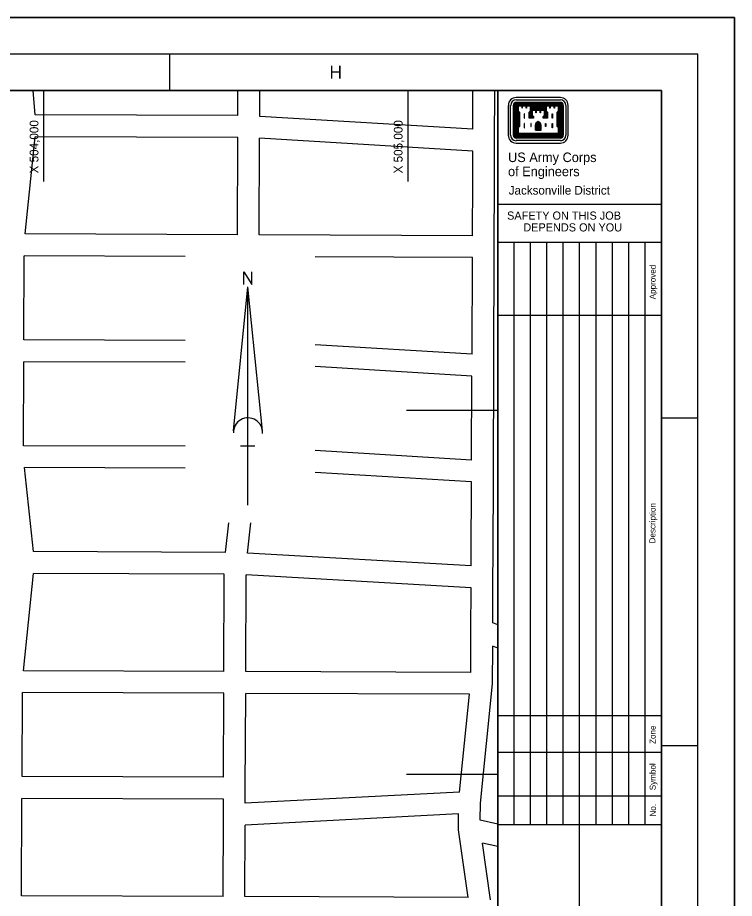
# Model space of a CAD drawing. Extents: x 497696 to 505896, y 1319278 to 1325078.
# Drawn here: x 503928 to 505896, y 1322658 to 1325078 of the extents above; entities that cross this region are included whole.
import ezdxf

# ---------------------------------------------------------------- set-up
doc = ezdxf.new("R2010")
doc.units = 0
for name, color, linetype in [('G-ANNO-SYMB', 7, 'Continuous'), ('G-ANNO-TEXT', 7, 'Continuous'), ('G-ANNO-TTLB', 7, 'Continuous'), ('Level 1', 7, 'Continuous'), ('Level 2', 7, 'Continuous'), ('Level 3', 7, 'Continuous'), ('Level 32', 7, 'Continuous')]:
    doc.layers.add(name, color=color, linetype=linetype)

msp = doc.modelspace()

# ---------------------------------------------------------------- linework, layer by layer
at = {"layer": 'G-ANNO-SYMB'}
for p, q in [((505418.4, 1324858.3), (505296.8, 1324858.3)), ((505275.4, 1324836.9), (505275.4, 1324754.9)), ((505281.8, 1324754.9), (505281.8, 1324836.9)), ((505288.8, 1324836.9), (505288.8, 1324754.9)), ((505290.6, 1324836.9), (505290.6, 1324754.9)), ((505292.2, 1324836.9), (505292.2, 1324754.9)), ((505294, 1324836.9), (505294, 1324754.9)), ((505295.8, 1324836.9), (505295.8, 1324754.9)), ((505296.8, 1324851.9), (505418.4, 1324851.9)), ((505418.4, 1324845.1), (505296.8, 1324845.1)), ((505418.4, 1324843.3), (505296.8, 1324843.3)), ((505418.4, 1324841.5), (505296.8, 1324841.5)), ((505418.4, 1324839.9), (505296.8, 1324839.9)), ((505418.4, 1324838.1), (505296.8, 1324838.1)), ((505297.6, 1324836.9), (505297.6, 1324755.5)), ((505299.2, 1324836.9), (505299.2, 1324757.3)), ((505339, 1324836.5), (505376.2, 1324836.5)), ((505339, 1324834.7), (505376.2, 1324834.7)), ((505339, 1324833.1), (505376.2, 1324833.1)), ((505339, 1324831.3), (505376.2, 1324831.3)), ((505339, 1324829.5), (505376.2, 1324829.5)), ((505416, 1324836.9), (505416, 1324757.3)), ((505417.6, 1324836.9), (505417.6, 1324755.5)), ((505419.4, 1324836.9), (505419.4, 1324754.9)), ((505421.2, 1324836.9), (505421.2, 1324754.9)), ((505422.8, 1324836.9), (505422.8, 1324754.9)), ((505424.6, 1324836.9), (505424.6, 1324754.9)), ((505426.4, 1324836.9), (505426.4, 1324754.9)), ((505433.2, 1324836.9), (505433.2, 1324754.9)), ((505439.8, 1324754.9), (505439.8, 1324836.9)), ((505300.6, 1324819.5), (505300.6, 1324777.5)), ((505302.4, 1324817.7), (505302.4, 1324779.5)), ((505339, 1324827.9), (505376.2, 1324827.9)), ((505339, 1324826.1), (505376.2, 1324826.1)), ((505412.8, 1324817.7), (505412.8, 1324779.5)), ((505414.6, 1324819.3), (505414.6, 1324777.7)), ((505349.6, 1324769.1), (505349.6, 1324782.5)), ((505351.2, 1324769.1), (505351.2, 1324782.5)), ((505353, 1324769.1), (505353, 1324782.5)), ((505354.8, 1324769.1), (505354.8, 1324782.5)), ((505356.4, 1324769.1), (505356.4, 1324782.5)), ((505358.8, 1324769.1), (505358.8, 1324782.5)), ((505360.4, 1324769.1), (505360.4, 1324782.5)), ((505362.2, 1324769.1), (505362.2, 1324782.5)), ((505364, 1324769.1), (505364, 1324782.5)), ((505365.6, 1324769.1), (505365.6, 1324782.5)), ((505416, 1324757.3), (505299.2, 1324757.3)), ((505349.6, 1324769.1), (505365.6, 1324769.1)), ((505418.4, 1324753.7), (505296.8, 1324753.7)), ((505418.4, 1324752.1), (505296.8, 1324752.1)), ((505418.4, 1324750.3), (505296.8, 1324750.3)), ((505418.4, 1324748.5), (505296.8, 1324748.5)), ((505418.4, 1324746.9), (505296.8, 1324746.9)), ((505418.4, 1324739.9), (505296.8, 1324739.9)), ((505296.8, 1324733.3), (505418.4, 1324733.3)), ((505417.6, 1324755.5), (505297.6, 1324755.5))]:
    msp.add_line(p, q, dxfattribs=at)
for points in [[(505300.6, 1324836.9), (505300.6, 1324821.1), (505304, 1324817.7), (505304, 1324779.5), (505300.6, 1324775.9), (505300.6, 1324758.5), (505414.6, 1324758.5), (505414.6, 1324775.9), (505411, 1324779.5), (505411, 1324817.7), (505414.6, 1324821.1), (505414.6, 1324836.9), (505399.6, 1324836.9), (505388, 1324836.9), (505377.2, 1324836.9), (505377.2, 1324821.1), (505381, 1324817.7), (505381, 1324803.7), (505372.6, 1324803.7), (505372.6, 1324805.1), (505376.2, 1324808.7), (505376.2, 1324824.3), (505361.2, 1324824.3), (505349.6, 1324824.3), (505339, 1324824.3), (505339, 1324808.7), (505342.6, 1324805.1), (505342.6, 1324803.7), (505334.2, 1324803.7), (505334.2, 1324817.7), (505337.8, 1324821.1), (505337.8, 1324836.9), (505322.8, 1324836.9), (505311.2, 1324836.9), (505300.6, 1324836.9)], [(505302.2, 1324835.1), (505302.2, 1324821.9), (505305.8, 1324818.3), (505305.8, 1324778.7), (505302.2, 1324775.1), (505302.2, 1324760.3), (505413, 1324760.3), (505413, 1324775.1), (505409.2, 1324778.7), (505409.2, 1324818.3), (505413, 1324821.9), (505413, 1324835.1), (505402.2, 1324835.1), (505402.2, 1324828.9), (505401.2, 1324828.9), (505401.2, 1324835.1), (505390.6, 1324835.1), (505390.6, 1324828.9), (505389.8, 1324828.9), (505389.8, 1324835.1), (505379, 1324835.1), (505379, 1324821.9), (505382.6, 1324818.3), (505382.6, 1324802.1), (505371, 1324802.1), (505371, 1324805.9), (505374.6, 1324809.5), (505374.6, 1324822.7), (505363.8, 1324822.7), (505363.8, 1324816.5), (505363, 1324816.5), (505363, 1324822.7), (505352.2, 1324822.7), (505352.2, 1324816.5), (505351.2, 1324816.5), (505351.2, 1324822.7), (505340.6, 1324822.7), (505340.6, 1324809.5), (505344.2, 1324805.9), (505344.2, 1324802.1), (505332.6, 1324802.1), (505332.6, 1324818.3), (505336.2, 1324821.9), (505336.2, 1324835.1), (505325.6, 1324835.1), (505325.6, 1324828.9), (505324.6, 1324828.9), (505324.6, 1324835.1), (505313.8, 1324835.1), (505313.8, 1324828.9), (505313, 1324828.9), (505313, 1324835.1), (505302.2, 1324835.1)], [(505318.6, 1324813.7), (505318.6, 1324802.1), (505319.8, 1324802.1), (505319.8, 1324813.7), (505318.6, 1324813.7)], [(505337, 1324817.9), (505336, 1324816.9), (505336, 1324805.5), (505339.8, 1324805.5), (505337.2, 1324808.1), (505337.2, 1324818.1)], [(505378.2, 1324817.9), (505379.2, 1324816.9), (505379.2, 1324805.5), (505375.6, 1324805.5), (505378, 1324808.1), (505378, 1324818.1)], [(505396.4, 1324813.7), (505396.4, 1324802.1), (505395.4, 1324802.1), (505395.4, 1324813.7), (505396.4, 1324813.7)], [(505318.6, 1324787.1), (505318.6, 1324775.3), (505319.8, 1324775.3), (505319.8, 1324787.1), (505318.6, 1324787.1)], [(505337, 1324787.1), (505337, 1324778.9), (505338, 1324778.9), (505338, 1324787.1), (505337, 1324787.1)], [(505378.2, 1324787.1), (505378.2, 1324778.9), (505377.2, 1324778.9), (505377.2, 1324787.1), (505378.2, 1324787.1)], [(505396.4, 1324787.1), (505396.4, 1324775.3), (505395.4, 1324775.3), (505395.4, 1324787.1), (505396.4, 1324787.1)]]:
    msp.add_lwpolyline(points, dxfattribs=at)
for centre, major_axis, start_param, end_param in [((505296.9, 1324836.9), (21.4, 0), 1.57078, 3.141576), ((505418.3, 1324836.9), (21.4, 0), 6.283169, 7.853965), ((505296.9, 1324836.9), (15, 0), 1.57078, 3.141576), ((505296.9, 1324836.9), (8.04, 0), 1.57078, 3.141576), ((505296.9, 1324836.9), (6.3, 0), 1.57078, 3.141576), ((505296.9, 1324836.9), (4.56, 0), 1.57078, 3.141576), ((505296.9, 1324836.9), (2.83, 0), 1.57078, 3.141576), ((505296.9, 1324836.9), (1.09, 0), 1.57078, 3.141576), ((505418.3, 1324836.9), (15, 0), 6.28317, 7.853966), ((505418.3, 1324836.9), (8.04, 0), 6.283169, 7.853965), ((505418.3, 1324836.9), (6.3, 0), 6.283169, 7.853965), ((505418.3, 1324836.9), (4.56, 0), 6.283169, 7.853965), ((505418.3, 1324836.9), (2.83, 0), 6.283169, 7.853965), ((505418.3, 1324836.9), (1.09, 0), 6.283169, 7.853965), ((505360.6, 1324781.6), (-11.1, 0), 4.985832, 6.214359), ((505360.6, 1324781.6), (-9.37, 0), 4.947465, 6.21436), ((505360.6, 1324781.6), (-7.63, 0), 4.947465, 6.21436), ((505360.6, 1324781.6), (-5.9, 0), 4.947465, 6.21436), ((505354.6, 1324781.6), (4.16, 0), 0.068794, 1.335689), ((505354.6, 1324781.6), (5.9, 0), 0.068794, 1.335689), ((505354.6, 1324781.6), (7.63, 0), 0.068795, 1.335689), ((505360.6, 1324781.6), (-4.16, 0), 4.947465, 6.214359), ((505354.6, 1324781.6), (9.37, 0), 0.068795, 1.335689), ((505354.6, 1324781.6), (11.1, 0), 0.068795, 1.29842), ((505296.8, 1324754.8), (-21.4, 0), 6.28317, 7.853966), ((505296.8, 1324754.8), (-15, 0), 6.28317, 7.853966), ((505296.8, 1324754.8), (-8.04, 0), 6.28317, 7.853966), ((505296.8, 1324754.8), (-6.3, 0), 6.28317, 7.853966), ((505296.8, 1324754.8), (-4.56, 0), 6.28317, 7.853966), ((505296.8, 1324754.8), (-2.83, 0), 6.28317, 7.853966), ((505296.8, 1324754.8), (-1.09, 0), 6.28317, 7.853966), ((505418.3, 1324754.8), (8.04, 0), 4.712373, 6.28317), ((505418.3, 1324754.8), (6.3, 0), 4.712373, 6.28317), ((505418.3, 1324754.8), (4.56, 0), 4.712373, 6.28317), ((505418.3, 1324754.8), (2.83, 0), 4.712373, 6.28317), ((505418.3, 1324754.8), (1.09, 0), 4.712373, 6.28317), ((505418.3, 1324754.8), (21.4, 0), 4.712373, 6.28317), ((505418.3, 1324754.8), (-15, 0), 1.570781, 3.141577)]:
    msp.add_ellipse(centre, major_axis=major_axis, ratio=0.99964, start_param=start_param, end_param=end_param, dxfattribs=at)
at = {"layer": 'G-ANNO-TTLB'}
for p, q in [((505796.2, 1324977.9), (497796.2, 1324977.9)), ((504346.2, 1324877.9), (504346.2, 1324977.9)), ((505796.2, 1319377.9), (505796.2, 1324977.9)), ((498046.2, 1324877.9), (505696.2, 1324877.9)), ((505246.2, 1319477.9), (505246.2, 1324877.9)), ((505696.2, 1324877.9), (505696.2, 1319477.9)), ((505696.2, 1324564.5), (505246.2, 1324564.5)), ((505291.2, 1322860.5), (505291.2, 1324460.3)), ((505336.2, 1322860.5), (505336.2, 1324460.3)), ((505381.2, 1322860.5), (505381.2, 1324460.3)), ((505426.2, 1322860.5), (505426.2, 1324460.3)), ((505471.2, 1322860.5), (505471.2, 1324460.3)), ((505516.2, 1322860.5), (505516.2, 1324460.3)), ((505561.2, 1322860.5), (505561.2, 1324460.3)), ((505606.2, 1322860.5), (505606.2, 1324460.3)), ((505651.2, 1322860.5), (505651.2, 1324460.3)), ((505246.2, 1324260.3), (505696.2, 1324260.3)), ((505796.2, 1323977.9), (505696.2, 1323977.9)), ((505246.2, 1323160.5), (505696.2, 1323160.5)), ((505796.2, 1323077.9), (505696.2, 1323077.9)), ((505246.2, 1323060.5), (505696.2, 1323060.5)), ((505246.2, 1322940.5), (505696.2, 1322940.5)), ((505469.6, 1322860.5), (505469.6, 1321820.7))]:
    msp.add_line(p, q, dxfattribs=at)
for points in [[(497696.2, 1319277.9), (505896.2, 1319277.9), (505896.2, 1325077.9), (497696.2, 1325077.9)], [(497696.2, 1319277.9), (505896.2, 1319277.9), (505896.2, 1325077.9), (497696.2, 1325077.9)], [(497696.2, 1325077.9), (505896.2, 1325077.9), (505896.2, 1319277.9), (497696.2, 1319277.9)]]:
    msp.add_lwpolyline(points, close=True, dxfattribs=at)
for points in [[(505846.2, 1325077.9), (505896.2, 1325077.9), (505896.2, 1325027.9)], [(505696.2, 1324460.3), (505246.2, 1324460.3)], [(505696.2, 1322860.5), (505246.2, 1322860.5)]]:
    msp.add_lwpolyline(points, dxfattribs=at)
at = {"layer": 'Level 1'}
for p, q in [((504346.2, 1324877.9), (504346.2, 1324977.9)), ((505246.2, 1324877.9), (505246.2, 1319477.9)), ((505796.2, 1323977.9), (505696.2, 1323977.9)), ((505796.2, 1323077.9), (505696.2, 1323077.9))]:
    msp.add_line(p, q, dxfattribs=at)
for points in [[(497796.2, 1319377.9), (505796.2, 1319377.9), (505796.2, 1324977.9), (497796.2, 1324977.9)], [(498046.2, 1319477.9), (505696.2, 1319477.9), (505696.2, 1324877.9), (498046.2, 1324877.9)]]:
    msp.add_lwpolyline(points, close=True, dxfattribs=at)
at = {"layer": 'Level 2'}
for p, q in [((504000, 1324627.9), (504000, 1324877.9)), ((505000, 1324627.9), (505000, 1324877.9)), ((504520.7, 1323942.4), (504560.5, 1324338.4)), ((504560.5, 1323738.4), (504560.5, 1324338.4)), ((504600.3, 1323942.4), (504560.5, 1324338.4)), ((504996.2, 1324000), (505246.2, 1324000)), ((504579.5, 1323900.4), (504539.5, 1323900.4)), ((504996.2, 1323000), (505246.2, 1323000))]:
    msp.add_line(p, q, dxfattribs=at)
msp.add_lwpolyline([(504549.5, 1324344.8), (504549.5, 1324379.8), (504571.2, 1324344.8), (504571.2, 1324379.8)], dxfattribs=at)
msp.add_arc((504560.5, 1323938.4), 40, 355.2984, 182.0673, dxfattribs=at)
at = {"layer": 'Level 32'}
for p, q in [((503976.5, 1324810.7), (503970.2, 1324877.9)), ((504532.6, 1324808.6), (504532.9, 1324877.9)), ((504592.6, 1324806.7), (504592.9, 1324877.9)), ((505178, 1324771.5), (505178.4, 1324877.9)), ((505237.9, 1324739.5), (505238.4, 1324877.9)), ((504532.6, 1324808.6), (503976.5, 1324810.7)), ((505178, 1324771.5), (504592.6, 1324806.7)), ((503948.9, 1324483.6), (503976.3, 1324750.7)), ((504532.4, 1324748.6), (503976.3, 1324750.7)), ((504531.4, 1324481.4), (504532.4, 1324748.6)), ((504591.4, 1324481.2), (504592.4, 1324746.6)), ((505177.8, 1324711.4), (504592.4, 1324746.6)), ((505237.7, 1324675.2), (505237.9, 1324739.5)), ((505177.7, 1324675.4), (505177.8, 1324711.4)), ((505177.5, 1324630.3), (505177.7, 1324675.4)), ((505237.5, 1324630.1), (505237.7, 1324675.2)), ((505176.9, 1324478.9), (505177.5, 1324630.3)), ((505236.8, 1324448.7), (505237.5, 1324630.1)), ((504531.4, 1324481.4), (503948.9, 1324483.6)), ((505176.9, 1324478.9), (504591.4, 1324481.2)), ((505235.5, 1324121.5), (505236.8, 1324448.7)), ((503944.7, 1324192.8), (503945.6, 1324423.7)), ((504387.6, 1324422), (503945.6, 1324423.7)), ((505176.7, 1324418.9), (504744.6, 1324420.6)), ((505175.7, 1324153.5), (505176.7, 1324418.9)), ((504387.6, 1324191.1), (503944.7, 1324192.8)), ((505175.7, 1324153.5), (504744.6, 1324179.4)), ((503943.6, 1323902), (503944.5, 1324132.8)), ((504387.6, 1324131.1), (503944.5, 1324132.8)), ((505175.4, 1324093.4), (504744.6, 1324119.3)), ((505234.4, 1323830.7), (505235.5, 1324121.5)), ((505174.5, 1323862.6), (505175.4, 1324093.4)), ((504387.6, 1323900.3), (503943.6, 1323902)), ((505174.5, 1323862.6), (504744.6, 1323888.5)), ((503971.6, 1323611), (503946.9, 1323842)), ((504387.6, 1323840.3), (503946.9, 1323842)), ((505174.3, 1323802.5), (504744.6, 1323828.4)), ((505233.5, 1323596.2), (505234.4, 1323830.7)), ((505173.5, 1323596.4), (505174.3, 1323802.5)), ((504498.9, 1323609), (504508.1, 1323689.7)), ((504559, 1323607), (504568.5, 1323689.7)), ((504498.9, 1323609), (503971.6, 1323611)), ((505173.4, 1323571.7), (504559, 1323607)), ((505173.4, 1323571.7), (505173.5, 1323596.4)), ((505233.3, 1323539.8), (505233.5, 1323596.2)), ((503944.3, 1323283.9), (503971.7, 1323551)), ((504495.5, 1323549), (503971.7, 1323551)), ((504494.5, 1323281.8), (504495.5, 1323549)), ((504554.5, 1323281.6), (504555.5, 1323547.1)), ((505173.2, 1323511.6), (504555.5, 1323547.1)), ((505232.8, 1323415.2), (505233.3, 1323539.8)), ((505172.8, 1323394.6), (505173.2, 1323511.6)), ((505246.2, 1323410.1), (505232.8, 1323415.2)), ((505172.3, 1323279.2), (505172.8, 1323394.6)), ((505232.2, 1323247.5), (505232.6, 1323351.1)), ((505246.2, 1323345.9), (505232.6, 1323351.1)), ((504494.5, 1323281.8), (503944.3, 1323283.9)), ((505172.3, 1323279.2), (504554.5, 1323281.6)), ((505198.7, 1322920.4), (505232.2, 1323247.5)), ((503940.1, 1322993.1), (503941, 1323223.9)), ((504494.2, 1323221.8), (503941, 1323223.9)), ((504493.4, 1322991), (504494.2, 1323221.8)), ((504553.2, 1322960.7), (504554.2, 1323221.6)), ((505169, 1323219.2), (504554.2, 1323221.6)), ((505141.4, 1322950.6), (505169, 1323219.2)), ((504493.4, 1322991), (503940.1, 1322993.1)), ((504553.1, 1322919.8), (504553.2, 1322960.7)), ((505141.4, 1322950.6), (504553.1, 1322919.8)), ((503938.8, 1322665.9), (503939.8, 1322933.1)), ((504493.1, 1322931), (503939.8, 1322933.1)), ((504493, 1322888.3), (504493.1, 1322931)), ((505198.5, 1322873.2), (505198.7, 1322920.4)), ((504492.1, 1322663.8), (504493, 1322888.3)), ((505138.5, 1322890.4), (504552.8, 1322859.7)), ((505138.4, 1322847.2), (505138.5, 1322890.4)), ((505246.2, 1322862.3), (505198.5, 1322873.2)), ((504552.1, 1322663.5), (504552.8, 1322859.7)), ((505165.2, 1322661.2), (505138.4, 1322847.2)), ((505226.8, 1322654.6), (505204.3, 1322810.3)), ((505246.2, 1322800.7), (505204.3, 1322810.3)), ((504492.1, 1322663.8), (503938.8, 1322665.9)), ((505165.2, 1322661.2), (504552.1, 1322663.5))]:
    msp.add_line(p, q, dxfattribs=at)

# ---------------------------------------------------------------- texts
at = {"layer": 'G-ANNO-TEXT'}
for s, height, p in [('US Army Corps', 26.172, (505274.6, 1324681.1)), ('of Engineers', 26.172, (505274.6, 1324642.3)), ('Jacksonville District', 23.8, (505276.6, 1324591.7)), ('SAFETY ON THIS JOB', 22.397, (505272, 1324522.9)), ('DEPENDS ON YOU', 22.397, (505316.6, 1324490.5))]:
    msp.add_text(s, height=height, dxfattribs=at).set_placement(p)
for s, height, p in [('Approved', 16.6, (505679.8, 1324304.1)), ('Description', 16.598, (505679.2, 1323633.5)), ('Zone', 16.6, (505679.8, 1323082.7)), ('Symbol', 16.6, (505680, 1322955.5)), ('No.', 16.6, (505680.6, 1322883.3))]:
    msp.add_text(s, height=height, rotation=89.6609, dxfattribs=at).set_placement(p)
at = {"layer": 'G-ANNO-TTLB'}
msp.add_text('H', height=35.7, dxfattribs=at).set_placement((504784.2, 1324910.1))
at = {"layer": 'Level 3'}
for s, p in [('X 504,000', (503985, 1324649.9)), ('X 505,000', (504985, 1324649.9))]:
    msp.add_text(s, height=24, rotation=90, dxfattribs=at).set_placement(p)

doc.saveas('drawing.dxf')
